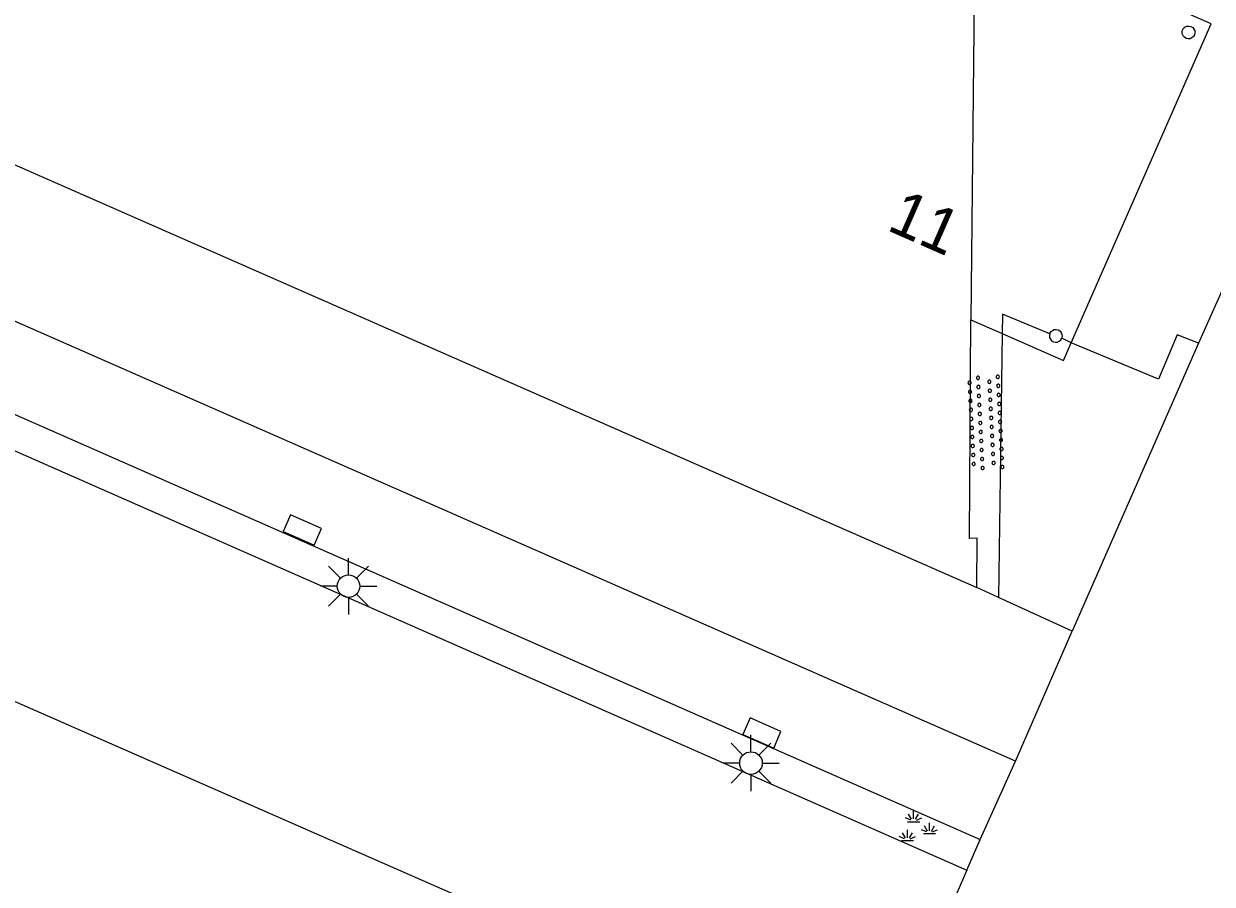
# Model space of a CAD drawing. Extents: x 131000 to 133013, y 393000 to 396501.
# Drawn here: x 131841.21 to 131867.55, y 394898.64 to 394917.7 of the extents above; entities that cross this region are included whole.
import ezdxf

# ---------------------------------------------------------------- set-up
doc = ezdxf.new("R2010")
doc.units = 0
for name, color, linetype in [('gg-anno-huisnummerreeks BGT', 7, 'Continuous'), ('gg-bbg-hoofdgebouw', 7, 'Continuous'), ('gg-bbg-onder overbouw', 7, 'Continuous'), ('gg-bbg-pand overbouw', 7, 'Continuous'), ('gg-bbg-pilaar onder overbouw', 7, 'Continuous'), ('gg-knt-verharding', 7, 'Continuous'), ('gg-knt-verharding nz', 7, 'Continuous'), ('gt-grn-vlakafsluiter', 7, 'Continuous'), ('gt-symb-groenvak', 7, 'Continuous'), ('gt-symb-kolk', 7, 'Continuous'), ('gt-symb-lichtmast', 7, 'Continuous'), ('gt-symb-overige verharding', 7, 'Continuous')]:
    doc.layers.add(name, color=color, linetype=linetype)

# ---------------------------------------------------------------- blocks, each defined once
blk = doc.blocks.new('gt0-OVH')
at = {"layer": 'gt-symb-overige verharding'}
for points in [[(-0.972, 0.298), (-0.967, 0.308), (-0.965, 0.319), (-0.966, 0.33), (-0.971, 0.34), (-0.978, 0.348), (-0.988, 0.353), (-0.999, 0.355), (-1.01, 0.354), (-1.02, 0.349), (-1.028, 0.342), (-1.033, 0.332), (-1.035, 0.321), (-1.034, 0.31), (-1.029, 0.3), (-1.022, 0.292), (-1.012, 0.287), (-1.001, 0.285), (-0.99, 0.286), (-0.98, 0.291)], [(-0.772, 0.298), (-0.767, 0.308), (-0.765, 0.319), (-0.766, 0.33), (-0.771, 0.34), (-0.778, 0.348), (-0.788, 0.353), (-0.799, 0.355), (-0.81, 0.354), (-0.82, 0.349), (-0.828, 0.342), (-0.833, 0.332), (-0.835, 0.321), (-0.834, 0.31), (-0.829, 0.3), (-0.822, 0.292), (-0.812, 0.287), (-0.801, 0.285), (-0.79, 0.286), (-0.78, 0.291)], [(-0.572, 0.298), (-0.567, 0.308), (-0.565, 0.319), (-0.566, 0.33), (-0.571, 0.34), (-0.578, 0.348), (-0.588, 0.353), (-0.599, 0.355), (-0.61, 0.354), (-0.62, 0.349), (-0.628, 0.342), (-0.633, 0.332), (-0.635, 0.321), (-0.634, 0.31), (-0.629, 0.3), (-0.622, 0.292), (-0.612, 0.287), (-0.601, 0.285), (-0.59, 0.286), (-0.58, 0.291)], [(-0.372, 0.298), (-0.367, 0.308), (-0.365, 0.319), (-0.366, 0.33), (-0.371, 0.34), (-0.378, 0.348), (-0.388, 0.353), (-0.399, 0.355), (-0.41, 0.354), (-0.42, 0.349), (-0.428, 0.342), (-0.433, 0.332), (-0.435, 0.321), (-0.434, 0.31), (-0.429, 0.3), (-0.422, 0.292), (-0.412, 0.287), (-0.401, 0.285), (-0.39, 0.286), (-0.38, 0.291)], [(-0.172, 0.298), (-0.167, 0.308), (-0.165, 0.319), (-0.166, 0.33), (-0.171, 0.34), (-0.178, 0.348), (-0.188, 0.353), (-0.199, 0.355), (-0.21, 0.354), (-0.22, 0.349), (-0.228, 0.342), (-0.233, 0.332), (-0.235, 0.321), (-0.234, 0.31), (-0.229, 0.3), (-0.222, 0.292), (-0.212, 0.287), (-0.201, 0.285), (-0.19, 0.286), (-0.18, 0.291)], [(0.028, 0.298), (0.033, 0.308), (0.035, 0.319), (0.034, 0.33), (0.029, 0.34), (0.022, 0.348), (0.012, 0.353), (0.001, 0.355), (-0.01, 0.354), (-0.02, 0.349), (-0.028, 0.342), (-0.033, 0.332), (-0.035, 0.321), (-0.034, 0.31), (-0.029, 0.3), (-0.022, 0.292), (-0.012, 0.287), (-0.001, 0.285), (0.01, 0.286), (0.02, 0.291)], [(0.228, 0.298), (0.233, 0.308), (0.235, 0.319), (0.234, 0.33), (0.229, 0.34), (0.222, 0.348), (0.212, 0.353), (0.201, 0.355), (0.19, 0.354), (0.18, 0.349), (0.172, 0.342), (0.167, 0.332), (0.165, 0.321), (0.166, 0.31), (0.171, 0.3), (0.178, 0.292), (0.188, 0.287), (0.199, 0.285), (0.21, 0.286), (0.22, 0.291)], [(0.428, 0.298), (0.433, 0.308), (0.435, 0.319), (0.434, 0.33), (0.429, 0.34), (0.422, 0.348), (0.412, 0.353), (0.401, 0.355), (0.39, 0.354), (0.38, 0.349), (0.372, 0.342), (0.367, 0.332), (0.365, 0.321), (0.366, 0.31), (0.371, 0.3), (0.378, 0.292), (0.388, 0.287), (0.399, 0.285), (0.41, 0.286), (0.42, 0.291)], [(0.628, 0.298), (0.633, 0.308), (0.635, 0.319), (0.634, 0.33), (0.629, 0.34), (0.622, 0.348), (0.612, 0.353), (0.601, 0.355), (0.59, 0.354), (0.58, 0.349), (0.572, 0.342), (0.567, 0.332), (0.565, 0.321), (0.566, 0.31), (0.571, 0.3), (0.578, 0.292), (0.588, 0.287), (0.599, 0.285), (0.61, 0.286), (0.62, 0.291)], [(0.828, 0.298), (0.833, 0.308), (0.835, 0.319), (0.834, 0.33), (0.829, 0.34), (0.822, 0.348), (0.812, 0.353), (0.801, 0.355), (0.79, 0.354), (0.78, 0.349), (0.772, 0.342), (0.767, 0.332), (0.765, 0.321), (0.766, 0.31), (0.771, 0.3), (0.778, 0.292), (0.788, 0.287), (0.799, 0.285), (0.81, 0.286), (0.82, 0.291)], [(1.028, 0.298), (1.033, 0.308), (1.035, 0.319), (1.034, 0.33), (1.029, 0.34), (1.022, 0.348), (1.012, 0.353), (1.001, 0.355), (0.99, 0.354), (0.98, 0.349), (0.972, 0.342), (0.967, 0.332), (0.965, 0.321), (0.966, 0.31), (0.971, 0.3), (0.978, 0.292), (0.988, 0.287), (0.999, 0.285), (1.01, 0.286), (1.02, 0.291)], [(-0.872, 0.106), (-0.867, 0.116), (-0.865, 0.126), (-0.866, 0.137), (-0.871, 0.147), (-0.878, 0.156), (-0.888, 0.161), (-0.899, 0.163), (-0.91, 0.162), (-0.92, 0.157), (-0.928, 0.15), (-0.933, 0.14), (-0.935, 0.129), (-0.934, 0.118), (-0.929, 0.108), (-0.922, 0.1), (-0.912, 0.095), (-0.901, 0.092), (-0.89, 0.094), (-0.88, 0.098)], [(-0.672, 0.106), (-0.667, 0.116), (-0.665, 0.126), (-0.666, 0.137), (-0.671, 0.147), (-0.678, 0.156), (-0.688, 0.161), (-0.699, 0.163), (-0.71, 0.162), (-0.72, 0.157), (-0.728, 0.15), (-0.733, 0.14), (-0.735, 0.129), (-0.734, 0.118), (-0.729, 0.108), (-0.722, 0.1), (-0.712, 0.095), (-0.701, 0.092), (-0.69, 0.094), (-0.68, 0.098)], [(-0.472, 0.106), (-0.467, 0.116), (-0.465, 0.126), (-0.466, 0.137), (-0.471, 0.147), (-0.478, 0.156), (-0.488, 0.161), (-0.499, 0.163), (-0.51, 0.162), (-0.52, 0.157), (-0.528, 0.15), (-0.533, 0.14), (-0.535, 0.129), (-0.534, 0.118), (-0.529, 0.108), (-0.522, 0.1), (-0.512, 0.095), (-0.501, 0.092), (-0.49, 0.094), (-0.48, 0.098)], [(-0.272, 0.106), (-0.267, 0.116), (-0.265, 0.126), (-0.266, 0.137), (-0.271, 0.147), (-0.278, 0.156), (-0.288, 0.161), (-0.299, 0.163), (-0.31, 0.162), (-0.32, 0.157), (-0.328, 0.15), (-0.333, 0.14), (-0.335, 0.129), (-0.334, 0.118), (-0.329, 0.108), (-0.322, 0.1), (-0.312, 0.095), (-0.301, 0.092), (-0.29, 0.094), (-0.28, 0.098)], [(-0.072, 0.106), (-0.067, 0.116), (-0.065, 0.126), (-0.066, 0.137), (-0.071, 0.147), (-0.078, 0.156), (-0.088, 0.161), (-0.099, 0.163), (-0.11, 0.162), (-0.12, 0.157), (-0.128, 0.15), (-0.133, 0.14), (-0.135, 0.129), (-0.134, 0.118), (-0.129, 0.108), (-0.122, 0.1), (-0.112, 0.095), (-0.101, 0.092), (-0.09, 0.094), (-0.08, 0.098)], [(0.128, 0.106), (0.133, 0.116), (0.135, 0.126), (0.134, 0.137), (0.129, 0.147), (0.122, 0.156), (0.112, 0.161), (0.101, 0.163), (0.09, 0.162), (0.08, 0.157), (0.072, 0.15), (0.067, 0.14), (0.065, 0.129), (0.066, 0.118), (0.071, 0.108), (0.078, 0.1), (0.088, 0.095), (0.099, 0.092), (0.11, 0.094), (0.12, 0.098)], [(0.328, 0.106), (0.333, 0.116), (0.335, 0.126), (0.334, 0.137), (0.329, 0.147), (0.322, 0.156), (0.312, 0.161), (0.301, 0.163), (0.29, 0.162), (0.28, 0.157), (0.272, 0.15), (0.267, 0.14), (0.265, 0.129), (0.266, 0.118), (0.271, 0.108), (0.278, 0.1), (0.288, 0.095), (0.299, 0.092), (0.31, 0.094), (0.32, 0.098)], [(0.528, 0.106), (0.533, 0.116), (0.535, 0.126), (0.534, 0.137), (0.529, 0.147), (0.522, 0.156), (0.512, 0.161), (0.501, 0.163), (0.49, 0.162), (0.48, 0.157), (0.472, 0.15), (0.467, 0.14), (0.465, 0.129), (0.466, 0.118), (0.471, 0.108), (0.478, 0.1), (0.488, 0.095), (0.499, 0.092), (0.51, 0.094), (0.52, 0.098)], [(0.728, 0.106), (0.733, 0.116), (0.735, 0.126), (0.734, 0.137), (0.729, 0.147), (0.722, 0.156), (0.712, 0.161), (0.701, 0.163), (0.69, 0.162), (0.68, 0.157), (0.672, 0.15), (0.667, 0.14), (0.665, 0.129), (0.666, 0.118), (0.671, 0.108), (0.678, 0.1), (0.688, 0.095), (0.699, 0.092), (0.71, 0.094), (0.72, 0.098)], [(0.928, 0.106), (0.933, 0.116), (0.935, 0.126), (0.934, 0.137), (0.929, 0.147), (0.922, 0.156), (0.912, 0.161), (0.901, 0.163), (0.89, 0.162), (0.88, 0.157), (0.872, 0.15), (0.867, 0.14), (0.865, 0.129), (0.866, 0.118), (0.871, 0.108), (0.878, 0.1), (0.888, 0.095), (0.899, 0.092), (0.91, 0.094), (0.92, 0.098)], [(-0.972, -0.142), (-0.967, -0.132), (-0.965, -0.121), (-0.966, -0.11), (-0.971, -0.1), (-0.978, -0.092), (-0.988, -0.087), (-0.999, -0.085), (-1.01, -0.086), (-1.02, -0.091), (-1.028, -0.098), (-1.033, -0.108), (-1.035, -0.119), (-1.034, -0.13), (-1.029, -0.14), (-1.022, -0.148), (-1.012, -0.153), (-1.001, -0.155), (-0.99, -0.154), (-0.98, -0.149)], [(-0.772, -0.142), (-0.767, -0.132), (-0.765, -0.121), (-0.766, -0.11), (-0.771, -0.1), (-0.778, -0.092), (-0.788, -0.087), (-0.799, -0.085), (-0.81, -0.086), (-0.82, -0.091), (-0.828, -0.098), (-0.833, -0.108), (-0.835, -0.119), (-0.834, -0.13), (-0.829, -0.14), (-0.822, -0.148), (-0.812, -0.153), (-0.801, -0.155), (-0.79, -0.154), (-0.78, -0.149)], [(-0.572, -0.142), (-0.567, -0.132), (-0.565, -0.121), (-0.566, -0.11), (-0.571, -0.1), (-0.578, -0.092), (-0.588, -0.087), (-0.599, -0.085), (-0.61, -0.086), (-0.62, -0.091), (-0.628, -0.098), (-0.633, -0.108), (-0.635, -0.119), (-0.634, -0.13), (-0.629, -0.14), (-0.622, -0.148), (-0.612, -0.153), (-0.601, -0.155), (-0.59, -0.154), (-0.58, -0.149)], [(-0.372, -0.142), (-0.367, -0.132), (-0.365, -0.121), (-0.366, -0.11), (-0.371, -0.1), (-0.378, -0.092), (-0.388, -0.087), (-0.399, -0.085), (-0.41, -0.086), (-0.42, -0.091), (-0.428, -0.098), (-0.433, -0.108), (-0.435, -0.119), (-0.434, -0.13), (-0.429, -0.14), (-0.422, -0.148), (-0.412, -0.153), (-0.401, -0.155), (-0.39, -0.154), (-0.38, -0.149)], [(-0.172, -0.142), (-0.167, -0.132), (-0.165, -0.121), (-0.166, -0.11), (-0.171, -0.1), (-0.178, -0.092), (-0.188, -0.087), (-0.199, -0.085), (-0.21, -0.086), (-0.22, -0.091), (-0.228, -0.098), (-0.233, -0.108), (-0.235, -0.119), (-0.234, -0.13), (-0.229, -0.14), (-0.222, -0.148), (-0.212, -0.153), (-0.201, -0.155), (-0.19, -0.154), (-0.18, -0.149)], [(0.028, -0.142), (0.033, -0.132), (0.035, -0.121), (0.034, -0.11), (0.029, -0.1), (0.022, -0.092), (0.012, -0.087), (0.001, -0.085), (-0.01, -0.086), (-0.02, -0.091), (-0.028, -0.098), (-0.033, -0.108), (-0.035, -0.119), (-0.034, -0.13), (-0.029, -0.14), (-0.022, -0.148), (-0.012, -0.153), (-0.001, -0.155), (0.01, -0.154), (0.02, -0.149)], [(0.228, -0.142), (0.233, -0.132), (0.235, -0.121), (0.234, -0.11), (0.229, -0.1), (0.222, -0.092), (0.212, -0.087), (0.201, -0.085), (0.19, -0.086), (0.18, -0.091), (0.172, -0.098), (0.167, -0.108), (0.165, -0.119), (0.166, -0.13), (0.171, -0.14), (0.178, -0.148), (0.188, -0.153), (0.199, -0.155), (0.21, -0.154), (0.22, -0.149)], [(0.428, -0.142), (0.433, -0.132), (0.435, -0.121), (0.434, -0.11), (0.429, -0.1), (0.422, -0.092), (0.412, -0.087), (0.401, -0.085), (0.39, -0.086), (0.38, -0.091), (0.372, -0.098), (0.367, -0.108), (0.365, -0.119), (0.366, -0.13), (0.371, -0.14), (0.378, -0.148), (0.388, -0.153), (0.399, -0.155), (0.41, -0.154), (0.42, -0.149)], [(0.628, -0.142), (0.633, -0.132), (0.635, -0.121), (0.634, -0.11), (0.629, -0.1), (0.622, -0.092), (0.612, -0.087), (0.601, -0.085), (0.59, -0.086), (0.58, -0.091), (0.572, -0.098), (0.567, -0.108), (0.565, -0.119), (0.566, -0.13), (0.571, -0.14), (0.578, -0.148), (0.588, -0.153), (0.599, -0.155), (0.61, -0.154), (0.62, -0.149)], [(0.828, -0.142), (0.833, -0.132), (0.835, -0.121), (0.834, -0.11), (0.829, -0.1), (0.822, -0.092), (0.812, -0.087), (0.801, -0.085), (0.79, -0.086), (0.78, -0.091), (0.772, -0.098), (0.767, -0.108), (0.765, -0.119), (0.766, -0.13), (0.771, -0.14), (0.778, -0.148), (0.788, -0.153), (0.799, -0.155), (0.81, -0.154), (0.82, -0.149)], [(1.028, -0.142), (1.033, -0.132), (1.035, -0.121), (1.034, -0.11), (1.029, -0.1), (1.022, -0.092), (1.012, -0.087), (1.001, -0.085), (0.99, -0.086), (0.98, -0.091), (0.972, -0.098), (0.967, -0.108), (0.965, -0.119), (0.966, -0.13), (0.971, -0.14), (0.978, -0.148), (0.988, -0.153), (0.999, -0.155), (1.01, -0.154), (1.02, -0.149)], [(-0.872, -0.334), (-0.867, -0.324), (-0.865, -0.314), (-0.866, -0.303), (-0.871, -0.293), (-0.878, -0.284), (-0.888, -0.279), (-0.899, -0.277), (-0.91, -0.278), (-0.92, -0.283), (-0.928, -0.29), (-0.933, -0.3), (-0.935, -0.311), (-0.934, -0.322), (-0.929, -0.332), (-0.922, -0.34), (-0.912, -0.345), (-0.901, -0.348), (-0.89, -0.346), (-0.88, -0.342)], [(-0.672, -0.334), (-0.667, -0.324), (-0.665, -0.314), (-0.666, -0.303), (-0.671, -0.293), (-0.678, -0.284), (-0.688, -0.279), (-0.699, -0.277), (-0.71, -0.278), (-0.72, -0.283), (-0.728, -0.29), (-0.733, -0.3), (-0.735, -0.311), (-0.734, -0.322), (-0.729, -0.332), (-0.722, -0.34), (-0.712, -0.345), (-0.701, -0.348), (-0.69, -0.346), (-0.68, -0.342)], [(-0.472, -0.334), (-0.467, -0.324), (-0.465, -0.314), (-0.466, -0.303), (-0.471, -0.293), (-0.478, -0.284), (-0.488, -0.279), (-0.499, -0.277), (-0.51, -0.278), (-0.52, -0.283), (-0.528, -0.29), (-0.533, -0.3), (-0.535, -0.311), (-0.534, -0.322), (-0.529, -0.332), (-0.522, -0.34), (-0.512, -0.345), (-0.501, -0.348), (-0.49, -0.346), (-0.48, -0.342)], [(-0.272, -0.334), (-0.267, -0.324), (-0.265, -0.314), (-0.266, -0.303), (-0.271, -0.293), (-0.278, -0.284), (-0.288, -0.279), (-0.299, -0.277), (-0.31, -0.278), (-0.32, -0.283), (-0.328, -0.29), (-0.333, -0.3), (-0.335, -0.311), (-0.334, -0.322), (-0.329, -0.332), (-0.322, -0.34), (-0.312, -0.345), (-0.301, -0.348), (-0.29, -0.346), (-0.28, -0.342)], [(-0.072, -0.334), (-0.067, -0.324), (-0.065, -0.314), (-0.066, -0.303), (-0.071, -0.293), (-0.078, -0.284), (-0.088, -0.279), (-0.099, -0.277), (-0.11, -0.278), (-0.12, -0.283), (-0.128, -0.29), (-0.133, -0.3), (-0.135, -0.311), (-0.134, -0.322), (-0.129, -0.332), (-0.122, -0.34), (-0.112, -0.345), (-0.101, -0.348), (-0.09, -0.346), (-0.08, -0.342)], [(0.128, -0.334), (0.133, -0.324), (0.135, -0.314), (0.134, -0.303), (0.129, -0.293), (0.122, -0.284), (0.112, -0.279), (0.101, -0.277), (0.09, -0.278), (0.08, -0.283), (0.072, -0.29), (0.067, -0.3), (0.065, -0.311), (0.066, -0.322), (0.071, -0.332), (0.078, -0.34), (0.088, -0.345), (0.099, -0.348), (0.11, -0.346), (0.12, -0.342)], [(0.328, -0.334), (0.333, -0.324), (0.335, -0.314), (0.334, -0.303), (0.329, -0.293), (0.322, -0.284), (0.312, -0.279), (0.301, -0.277), (0.29, -0.278), (0.28, -0.283), (0.272, -0.29), (0.267, -0.3), (0.265, -0.311), (0.266, -0.322), (0.271, -0.332), (0.278, -0.34), (0.288, -0.345), (0.299, -0.348), (0.31, -0.346), (0.32, -0.342)], [(0.528, -0.334), (0.533, -0.324), (0.535, -0.314), (0.534, -0.303), (0.529, -0.293), (0.522, -0.284), (0.512, -0.279), (0.501, -0.277), (0.49, -0.278), (0.48, -0.283), (0.472, -0.29), (0.467, -0.3), (0.465, -0.311), (0.466, -0.322), (0.471, -0.332), (0.478, -0.34), (0.488, -0.345), (0.499, -0.348), (0.51, -0.346), (0.52, -0.342)], [(0.728, -0.334), (0.733, -0.324), (0.735, -0.314), (0.734, -0.303), (0.729, -0.293), (0.722, -0.284), (0.712, -0.279), (0.701, -0.277), (0.69, -0.278), (0.68, -0.283), (0.672, -0.29), (0.667, -0.3), (0.665, -0.311), (0.666, -0.322), (0.671, -0.332), (0.678, -0.34), (0.688, -0.345), (0.699, -0.348), (0.71, -0.346), (0.72, -0.342)], [(0.928, -0.334), (0.933, -0.324), (0.935, -0.314), (0.934, -0.303), (0.929, -0.293), (0.922, -0.284), (0.912, -0.279), (0.901, -0.277), (0.89, -0.278), (0.88, -0.283), (0.872, -0.29), (0.867, -0.3), (0.865, -0.311), (0.866, -0.322), (0.871, -0.332), (0.878, -0.34), (0.888, -0.345), (0.899, -0.348), (0.91, -0.346), (0.92, -0.342)]]:
    blk.add_lwpolyline(points, close=True, dxfattribs=at)
blk = doc.blocks.new('gt0-GRVAK')
at = {"layer": 'gt-symb-groenvak'}
for p, q in [((-0.091, 0.211), (-0.156, 0.322)), ((-0.047, 0.214), (-0.047, 0.393)), ((-0.004, 0.211), (0.061, 0.322)), ((-0.11, 0.189), (-0.228, 0.24)), ((-0.182, 0.153), (0.088, 0.153)), ((0.015, 0.189), (0.133, 0.24)), ((0.262, -0.052), (0.197, 0.059)), ((0.305, -0.049), (0.305, 0.13)), ((0.349, -0.052), (0.414, 0.059)), ((-0.245, -0.228), (-0.363, -0.177)), ((-0.226, -0.206), (-0.291, -0.095)), ((-0.183, -0.203), (-0.183, -0.024)), ((-0.139, -0.206), (-0.074, -0.095)), ((-0.12, -0.228), (-0.002, -0.177)), ((0.243, -0.074), (0.125, -0.023)), ((0.17, -0.11), (0.441, -0.11)), ((0.368, -0.074), (0.486, -0.023)), ((-0.318, -0.264), (-0.047, -0.264))]:
    blk.add_line(p, q, dxfattribs=at)
blk = doc.blocks.new('gt0-LMAST')
at = {"layer": 'gt-symb-lichtmast'}
for p, q in [((-0.005, 0.246), (-0.005, 0.621)), ((-0.182, 0.173), (-0.447, 0.438)), ((0.172, 0.173), (0.437, 0.438)), ((-0.255, -0.004), (-0.63, -0.004)), ((-0.182, -0.181), (-0.447, -0.446)), ((-0.005, -0.254), (-0.005, -0.629)), ((0.437, -0.446), (0.172, -0.181)), ((0.245, -0.004), (0.62, -0.004))]:
    blk.add_line(p, q, dxfattribs=at)
blk.add_circle((-0.005, -0.004), 0.25, dxfattribs=at)
blk = doc.blocks.new('gt0-KOLK')
at = {"layer": 'gt-symb-kolk'}
blk.add_lwpolyline([(0, 0), (0.375, 0), (0.375, 0.4), (-0.375, 0.4), (-0.375, 0), (0, 0)], dxfattribs=at)

msp = doc.modelspace()

# ---------------------------------------------------------------- linework, layer by layer
at = {"layer": 'gg-bbg-hoofdgebouw'}
msp.add_line((131833.218, 394917.992), (131862.333, 394905.215), dxfattribs=at)
msp.add_lwpolyline([(131862.333, 394905.215), (131862.341, 394906.303), (131862.166, 394906.299), (131862.202, 394911.141)], dxfattribs=at)
at = {"layer": 'gg-bbg-onder overbouw'}
msp.add_line((131862.294, 394919.995), (131862.202, 394911.141), dxfattribs=at)
at = {"layer": 'gg-bbg-pand overbouw'}
msp.add_line((131862.202, 394911.141), (131862.896, 394910.836), dxfattribs=at)
for points in [[(131864.425, 394910.635), (131867.527, 394917.7), (131864.216, 394919.152)], [(131862.896, 394910.836), (131864.252, 394910.24), (131864.425, 394910.635)]]:
    msp.add_lwpolyline(points, dxfattribs=at)
at = {"layer": 'gg-bbg-pilaar onder overbouw'}
for points in [[(131866.89, 394917.556), (131866.915, 394917.599), (131866.948, 394917.628), (131866.989, 394917.645), (131867.033, 394917.649), (131867.077, 394917.638), (131867.115, 394917.615), (131867.144, 394917.582), (131867.161, 394917.541), (131867.164, 394917.497), (131867.154, 394917.454), (131867.131, 394917.416), (131867.098, 394917.387), (131867.057, 394917.369), (131867.013, 394917.366), (131866.969, 394917.376), (131866.931, 394917.399), (131866.902, 394917.433), (131866.885, 394917.473), (131866.882, 394917.518), (131866.89, 394917.556)], [(131863.949, 394910.835), (131863.94, 394910.797), (131863.944, 394910.753), (131863.961, 394910.712), (131863.99, 394910.678), (131864.028, 394910.655), (131864.071, 394910.645), (131864.115, 394910.649), (131864.156, 394910.666), (131864.19, 394910.695), (131864.213, 394910.733)], [(131863.949, 394910.835), (131863.95, 394910.84), (131863.973, 394910.878), (131864.007, 394910.907), (131864.048, 394910.924), (131864.092, 394910.928), (131864.135, 394910.918), (131864.173, 394910.895), (131864.202, 394910.861), (131864.219, 394910.82), (131864.223, 394910.776), (131864.213, 394910.733)]]:
    msp.add_lwpolyline(points, dxfattribs=at)
at = {"layer": 'gg-knt-verharding'}
for p, q in [((131825.716, 394914.966), (131862.112, 394898.951)), ((131868.052, 394912.425), (131867.245, 394910.623)), ((131862.896, 394910.836), (131862.814, 394904.993)), ((131862.814, 394904.993), (131862.333, 394905.215)), ((131864.442, 394904.245), (131862.814, 394904.993)), ((131863.19, 394901.369), (131864.442, 394904.245)), ((131862.405, 394899.633), (131863.19, 394901.369)), ((131862.112, 394898.951), (131862.405, 394899.633)), ((131862.112, 394898.951), (131860.053, 394894.294))]:
    msp.add_line(p, q, dxfattribs=at)
for points in [[(131830.009, 394926.589), (131828.074, 394927.478), (131823.42, 394916.74), (131826.985, 394915.22), (131862.405, 394899.633)], [(131867.245, 394910.623), (131866.769, 394910.812), (131866.36, 394909.828), (131864.425, 394910.635)]]:
    msp.add_lwpolyline(points, dxfattribs=at)
at = {"layer": 'gg-knt-verharding nz'}
msp.add_line((131864.425, 394910.635), (131864.213, 394910.733), dxfattribs=at)
for points in [[(131863.19, 394901.369), (131826.128, 394917.644), (131830.009, 394926.589)], [(131825.716, 394914.966), (131823.686, 394910.287), (131853.317, 394897.29), (131860.053, 394894.294)], [(131863.949, 394910.835), (131862.902, 394911.27), (131862.896, 394910.836)]]:
    msp.add_lwpolyline(points, dxfattribs=at)
at = {"layer": 'gt-grn-vlakafsluiter'}
msp.add_line((131867.245, 394910.623), (131864.442, 394904.245), dxfattribs=at)

# ---------------------------------------------------------------- block references
at = {"layer": 'gt-symb-groenvak'}
msp.add_blockref('gt0-GRVAK', (131860.977, 394899.871), dxfattribs=at)
at = {"layer": 'gt-symb-kolk'}
for p, rotation in [((131847.301, 394906.303), -23.822899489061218), ((131857.487, 394901.806), -23.822899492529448)]:
    msp.add_blockref('gt0-KOLK', p, dxfattribs=dict(at, rotation=rotation))
at = {"layer": 'gt-symb-lichtmast'}
for p in [(131848.414, 394905.244), (131857.331, 394901.328)]:
    msp.add_blockref('gt0-LMAST', p, dxfattribs=at)
at = {"layer": 'gt-symb-overige verharding', "rotation": -87.07752733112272}
msp.add_blockref('gt0-OVH', (131862.528, 394908.864), dxfattribs=at)

# ---------------------------------------------------------------- texts
at = {"layer": 'gg-anno-huisnummerreeks BGT'}
msp.add_text('11', height=1, rotation=336.3, dxfattribs=at).set_placement((131860.309, 394913.141))

doc.saveas('drawing.dxf')
